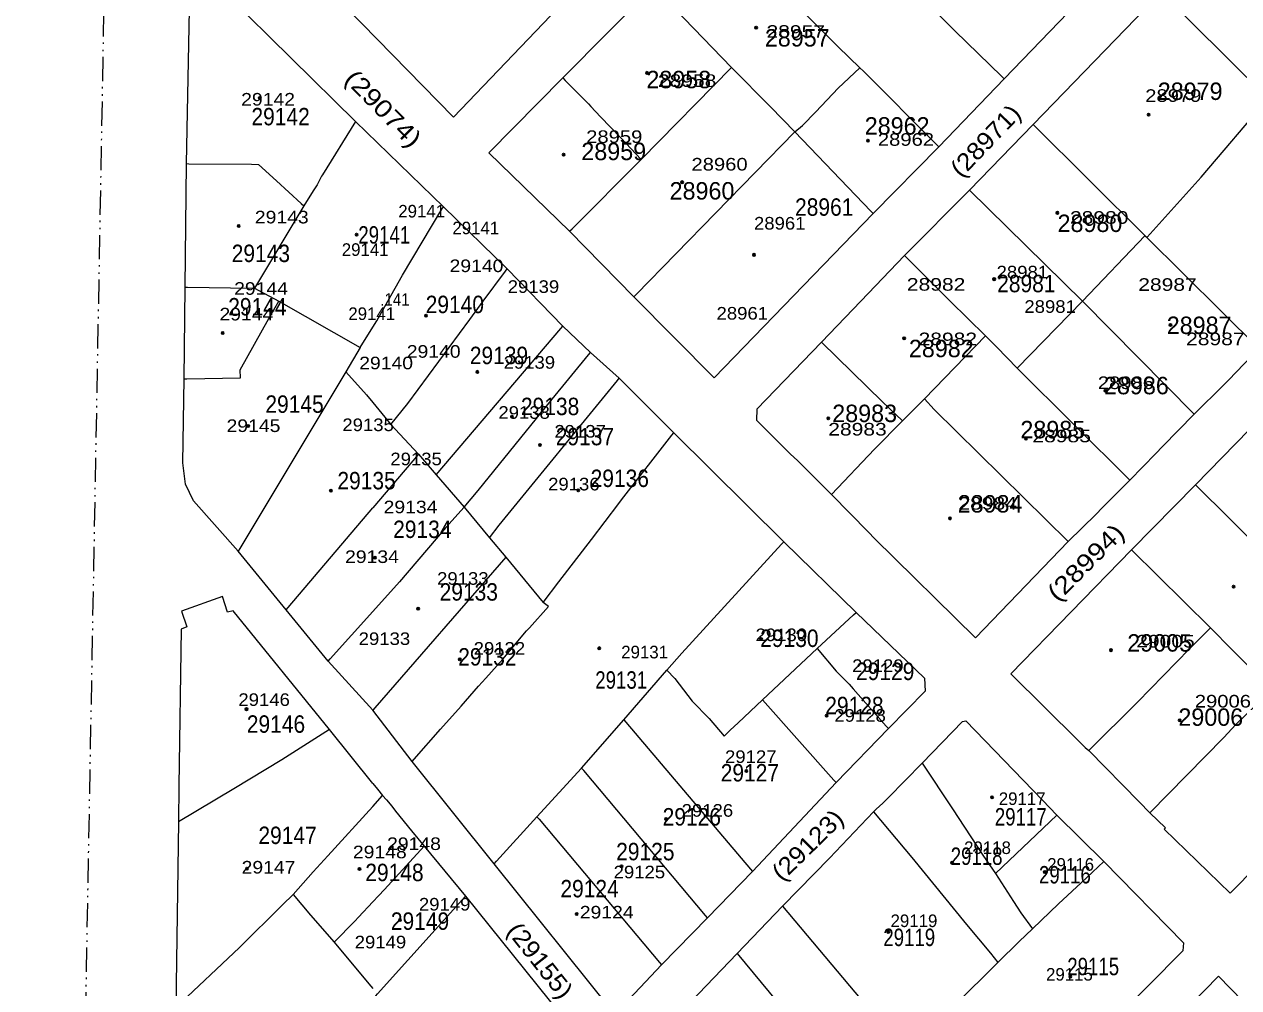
# Model space of a CAD drawing. Extents: x 650553 to 652508, y 239277 to 241647.
# Drawn here: x 650553 to 650803.9, y 240108.2 to 240307.2 of the extents above; entities that cross this region are included whole.
import ezdxf

# ---------------------------------------------------------------- set-up
doc = ezdxf.new("R2010")
doc.units = 0
doc.header["$PDMODE"] = 32
doc.header["$PDSIZE"] = 0.5
doc.linetypes.add('DASH_DOUBLE_DOT', pattern=[9.2, 5, -1.2, 0.3, -1.2, 0.3, -1.2])
for name, color, linetype in [('19', 7, 'Continuous'), ('20', 7, 'Continuous'), ('6', 7, 'Continuous')]:
    doc.layers.add(name, color=color, linetype=linetype)
for name, color, linetype, lineweight in [('3', 7, 'Continuous', 13), ('5', 7, 'Continuous', 13), ('52', 7, 'DASH_DOUBLE_DOT', 13)]:
    doc.layers.add(name, color=color, linetype=linetype, lineweight=lineweight)

msp = doc.modelspace()

# ---------------------------------------------------------------- linework, layer by layer
at = {"layer": '3'}
for p, q in [((650761.43, 240286.46), (650787.85, 240313.79)), ((650585.4, 240182.22), (650584.96, 240149.87)), ((650747.53, 240163.28), (650763.332, 240146.889)), ((650772.9, 240157.17), (650783.334, 240146.554)), ((650584.96, 240149.87), (650584.86, 240142.48)), ((650625, 240150.39), (650625.971, 240149.185)), ((650625.971, 240149.185), (650627.03, 240147.87)), ((650763.332, 240146.889), (650766.31, 240143.8)), ((650783.334, 240146.554), (650785.53, 240144.32))]:
    msp.add_line(p, q, dxfattribs=at)
for points in [[(650783.69, 240471.83), (650801.22, 240451.56), (650782.65, 240432.42), (650769.138, 240418.737), (650755.97, 240405.5), (650742.6, 240391.77), (650729.33, 240378.23), (650715.86, 240364.33), (650702.52, 240350.9), (650689.09, 240337.28), (650675.83, 240323.79), (650664.78, 240312.19), (650641.7, 240288.01), (650622.73, 240307.37), (650608.29, 240321.94)], [(650779.71, 240413.95), (650806.93, 240441.68), (650809.94, 240441.52), (650829.64, 240418.33), (650839.71, 240406.79), (650850.75, 240393.72), (650839.03, 240381.99), (650828.2, 240370.72), (650808.21, 240350.23), (650794.9, 240336.56), (650781.8, 240323.07), (650768.64, 240309.58), (650755.41, 240295.93), (650741.91, 240281.85), (650728.35, 240268.09)], [(650648.95, 240280.64), (650664.24, 240296.1), (650682.98, 240315.02), (650695.81, 240328), (650709.21, 240341.41), (650722.53, 240355.03), (650735.95, 240368.92), (650749.1, 240382.41), (650762.42, 240396.35), (650779.71, 240413.95)], [(650586.52, 240278.39), (650587.14, 240310.13), (650587.44, 240310.18), (650587.09, 240311.44), (650593.87, 240314.16), (650594.4, 240313.05), (650594.86, 240313.35), (650621.45, 240287.07), (650639.57, 240269.49), (650652.76, 240256.68), (650664.23, 240244.84), (650669.94, 240239.41), (650675.92, 240234.11), (650687.16, 240222.82), (650709.87, 240200.29), (650724.82, 240185.65), (650738.96, 240172.09)], [(650725.8, 240250), (650734.8, 240259.41), (650748.27, 240272.9), (650761.43, 240286.46)], [(650728.35, 240268.09), (650695.5, 240234.15), (650678.93, 240250.88), (650665.65, 240264.42), (650648.95, 240280.64)], [(650597.22, 240198.38), (650587.95, 240208.74), (650586.29, 240212.17), (650585.75, 240216.62), (650586.05, 240233.97), (650586.25, 240252.86), (650586.52, 240278.39)], [(650725.8, 240250), (650717.68, 240241.5), (650704.33, 240227.66), (650704.28, 240225.38), (650711.26, 240218.39), (650712.71, 240217.11), (650719.74, 240210.07), (650727.37, 240202.26), (650728.66, 240201), (650749.48, 240180.42), (650768.67, 240200.35), (650774.4, 240206.01), (650775.68, 240207.3), (650781.35, 240212.99), (650786.73, 240218.51), (650788.1, 240219.97), (650794.65, 240226.67), (650800.78, 240232.68), (650801.8, 240233.71), (650808, 240240.22), (650817.4, 240250)], [(650831.89, 240250), (650827.51, 240245.39), (650826.78, 240244.72), (650824.86, 240242.62), (650811.56, 240229.04), (650794.97, 240212.04), (650781.7, 240198.63), (650756.76, 240173.01), (650770.74, 240159.15), (650772.14, 240157.81), (650772.9, 240157.17)], [(650684.63, 240112.92), (650675.75, 240103.49), (650675.1, 240103.3), (650674.4, 240103.48), (650650.06, 240133.8), (650633.1, 240154.9), (650625, 240165.49), (650615.76, 240175.61), (650607.07, 240186.25), (650597.22, 240198.38)], [(650625, 240150.39), (650616.08, 240161.49), (650596.14, 240186.02), (650594.99, 240185.77), (650593.92, 240188.96), (650585.48, 240185.96), (650586.6, 240182.71), (650585.4, 240182.22)], [(650738.96, 240172.09), (650739.08, 240169.46), (650731.5, 240161.73), (650720.7, 240150.55), (650703.44, 240132.18), (650694.13, 240122.61), (650684.63, 240112.92)], [(650738.46, 240154.55), (650746.78, 240163.17), (650747.53, 240163.28)], [(650730.35, 240146.28), (650731.469, 240147.421), (650738.46, 240154.55)], [(650627.03, 240147.87), (650627.81, 240146.98), (650628.91, 240145.67), (650629.67, 240144.63), (650632.98, 240140.56), (650635.6, 240137.45), (650644.17, 240127.09), (650668.82, 240096.43), (650660.31, 240087.35), (650659.16, 240086.06), (650650.76, 240077.36), (650641.23, 240067.58), (650640.54, 240066.69), (650639.28, 240065.35), (650631.76, 240057.45)], [(650722.23, 240045.33), (650706.03, 240065.22), (650694.03, 240079.52), (650692.93, 240080.91), (650681.09, 240095.37), (650690.7, 240105.26), (650700.25, 240115.22), (650709.61, 240125), (650719.43, 240135), (650720.58, 240136.24), (650728.45, 240144.48), (650729.01, 240145.07), (650730.35, 240146.28)], [(650785.53, 240144.32), (650788.76, 240141.22), (650788.44, 240140.92), (650802.1, 240127.68), (650807.72, 240133.44), (650807.48, 240133.9), (650818.42, 240144.86)], [(650584.86, 240142.48), (650584.29, 240104.07), (650583.64, 240060.91)], [(650766.31, 240143.8), (650775.98, 240134.27), (650792.47, 240117.44), (650792.29, 240115.83), (650763.49, 240086.71), (650744.41, 240067.5), (650736.33, 240059.47), (650735.05, 240058.07), (650734.43, 240057.51), (650722.23, 240045.33)], [(650791.13, 240101.84), (650799.66, 240110.57), (650812.24, 240097.72)]]:
    msp.add_lwpolyline(points, dxfattribs=at)
at = {"layer": '5'}
for p, q in [((650748.27, 240272.9), (650771.6, 240250)), ((650784.48, 240263.5), (650771.6, 240250)), ((650734.8, 240259.41), (650744.29, 240250)), ((650628.12, 240250), (650631.11, 240255.33)), ((650758.13, 240236.16), (650771.6, 240250)), ((650771.6, 240250), (650794.65, 240226.67)), ((650622.4, 240240.42), (650619.4, 240235.41)), ((650634.41, 240218.37), (650625, 240207.31)), ((650649.13, 240201.13), (650651.11, 240203.69)), ((650685.71, 240173.76), (650688.84, 240177.29)), ((650625, 240145.64), (650627.03, 240147.87)), ((650753.65, 240131.76), (650766.31, 240143.8))]:
    msp.add_line(p, q, dxfattribs=at)
for points in [[(650709.21, 240341.41), (650709.71, 240340.917), (650732.07, 240318.85), (650737.83, 240313.19), (650745.26, 240305.8)], [(650695.81, 240328), (650696.307, 240327.5), (650717.06, 240306.61), (650721.14, 240302.53), (650725.63, 240298.21), (650726.33, 240297.51)], [(650784.94, 240263.21), (650796.11, 240275.63), (650809.97, 240291.87), (650823.52, 240304.87), (650836.94, 240317.85)], [(650682.98, 240315.02), (650683.461, 240314.52), (650699.12, 240298.24), (650707.18, 240290.13), (650712.21, 240284.96)], [(650787.85, 240313.79), (650801.15, 240300.62), (650809.97, 240291.87), (650834.26, 240267.54)], [(650745.26, 240305.8), (650754.91, 240296.416), (650755.41, 240295.93)], [(650665.65, 240264.42), (650666.148, 240264.92), (650680.45, 240279.27), (650699.12, 240298.24)], [(650712.21, 240284.96), (650713.76, 240286.28), (650716.53, 240289.09), (650721.14, 240293.99), (650725.63, 240298.21)], [(650726.33, 240297.51), (650741.413, 240282.35), (650741.91, 240281.85)], [(650664.24, 240296.1), (650664.733, 240295.6), (650669.52, 240290.74), (650670.06, 240290.18), (650672.04, 240288.05), (650676.2, 240283.72), (650680.45, 240279.27)], [(650621.45, 240287.07), (650614.62, 240276.09), (650614.38, 240275.8), (650614.11, 240275.29), (650613.51, 240274.05), (650612.65, 240272.8), (650610.73, 240269.71), (650600.55, 240252.65), (650605.56, 240250)], [(650678.93, 240250.88), (650679.418, 240251.38), (650712.21, 240284.96)], [(650712.21, 240284.96), (650727.872, 240268.59), (650728.35, 240268.09)], [(650761.43, 240286.46), (650784.682, 240263.372), (650808, 240240.22)], [(650586.52, 240278.39), (650587.02, 240278.386), (650599.97, 240278.29), (650601.42, 240278.23), (650605.11, 240274.84), (650610.23, 240270.166), (650610.73, 240269.71)], [(650631.11, 240255.33), (650639.271, 240268.99), (650639.57, 240269.49)], [(650784.48, 240263.5), (650784.682, 240263.372), (650784.94, 240263.21)], [(650647.82, 240250), (650652.39, 240256.18), (650652.76, 240256.68)], [(650586.25, 240252.86), (650586.75, 240252.853), (650600.05, 240252.657), (650600.55, 240252.65)], [(650586.05, 240233.97), (650586.55, 240233.979), (650597.65, 240234.18), (650597.59, 240235.79), (650603.53, 240246.38), (650605.56, 240250)], [(650605.56, 240250), (650622.4, 240240.42), (650625, 240244.6)], [(650625, 240244.6), (650625.84, 240245.95), (650628.12, 240250)], [(650628.75, 240224.5), (650632.23, 240228.86), (650645.03, 240246.23), (650647.82, 240250)], [(650744.29, 240250), (650751.53, 240242.83), (650753.87, 240240.5), (650758.13, 240236.16), (650781.35, 240212.99)], [(650638.08, 240214.09), (650663.805, 240244.34), (650664.23, 240244.84)], [(650719.74, 240210.07), (650728.65, 240219.44), (650734.43, 240225.26), (650738.95, 240229.79), (650751.53, 240242.83)], [(650662.08, 240229.72), (650669.534, 240238.91), (650669.94, 240239.41)], [(650717.68, 240241.5), (650730.31, 240229.17), (650734.43, 240225.26)], [(650619.4, 240235.41), (650597.519, 240198.88), (650597.22, 240198.38)], [(650619.4, 240235.41), (650623.72, 240230.66), (650625, 240229.09)], [(650651.11, 240203.69), (650675.512, 240233.61), (650675.92, 240234.11)], [(650643.85, 240207.42), (650646.79, 240210.87), (650662.08, 240229.72)], [(650738.95, 240229.79), (650740.98, 240227.59), (650768.67, 240200.35)], [(650625, 240229.09), (650628.75, 240224.5), (650630.61, 240222.52), (650634.41, 240218.37), (650638.08, 240214.09), (650643.85, 240207.42), (650649.13, 240201.13), (650652.5, 240197.09), (650660.18, 240187.72)], [(650676.36, 240208.98), (650686.77, 240222.32), (650687.16, 240222.82)], [(650794.97, 240212.04), (650816.57, 240190.66), (650824.01, 240183.28), (650840.42, 240167.09)], [(650607.07, 240186.25), (650607.496, 240186.75), (650625, 240207.31)], [(650643.85, 240207.42), (650640.08, 240203.25), (650630.5, 240192.02), (650625, 240185.9)], [(650633.1, 240154.9), (650633.542, 240155.4), (650639.01, 240161.58), (650643.26, 240166.37), (650646.85, 240170.44), (650648.37, 240172.11), (650651.87, 240176.06), (650656.74, 240181.88), (650657.38, 240182.53), (650661.29, 240186.89), (650660.18, 240187.72), (650663.42, 240192), (650670.18, 240200.77), (650675.85, 240208.18), (650676.36, 240208.98)], [(650688.84, 240177.29), (650709.413, 240199.79), (650709.87, 240200.29)], [(650652.5, 240197.09), (650625.435, 240165.99), (650625, 240165.49)], [(650781.7, 240198.63), (650798.02, 240182.54), (650802.52, 240177.97), (650810.6, 240169.99), (650808.01, 240167.19), (650807.31, 240166.49), (650824.01, 240150.65)], [(650615.76, 240175.61), (650616.209, 240176.11), (650625, 240185.9)], [(650716.79, 240178.22), (650724.32, 240185.187), (650724.82, 240185.65)], [(650772.9, 240157.17), (650782.96, 240167.19), (650793.69, 240178.18), (650798.02, 240182.54)], [(650685.71, 240173.76), (650687.38, 240172.02), (650691, 240167.39), (650694.45, 240163.8), (650697.55, 240160.11), (650698.8, 240161.37), (650700.44, 240162.91), (650705.47, 240167.63), (650716.79, 240178.22)], [(650716.79, 240178.22), (650720.7, 240173.58), (650723.42, 240170.85), (650724.23, 240169.89)], [(650650.06, 240133.8), (650650.517, 240134.3), (650658.91, 240143.49), (650668.14, 240153.56), (650676.86, 240163.5), (650685.71, 240173.76)], [(650724.23, 240169.89), (650731.055, 240162.23), (650731.5, 240161.73)], [(650705.47, 240167.63), (650720.254, 240151.05), (650720.7, 240150.55)], [(650785.53, 240144.32), (650800.78, 240159.87), (650803.27, 240162.56), (650807.31, 240166.49)], [(650616.08, 240161.49), (650606.19, 240155.28), (650596.26, 240149.23), (650584.86, 240142.48)], [(650676.86, 240163.5), (650677.284, 240163), (650703.016, 240132.68), (650703.44, 240132.18)], [(650738.46, 240154.55), (650744.74, 240145.12), (650751.03, 240135.56), (650753.65, 240131.76), (650757.32, 240126.02), (650758.86, 240123.64), (650761.29, 240120.34)], [(650694.13, 240122.61), (650693.71, 240123.11), (650668.56, 240153.06), (650668.14, 240153.56)], [(650584.29, 240104.07), (650597.45, 240116.5), (650606.31, 240125.29), (650608.58, 240127.45), (650612.66, 240132.09), (650615.73, 240135.44), (650625, 240145.64)], [(650728.45, 240144.48), (650736.35, 240135.05), (650747.62, 240121.24), (650752.6, 240115.32), (650754.11, 240113.42)], [(650658.91, 240143.49), (650659.331, 240142.99), (650684.209, 240113.42), (650684.63, 240112.92)], [(650625, 240125.89), (650626.18, 240127.14), (650627.39, 240128.48), (650635.6, 240137.45)], [(650715.45, 240074.54), (650713.99, 240076.53), (650712.37, 240078.72), (650710.08, 240081.83), (650720.2, 240091.4), (650722, 240089.82), (650725.8, 240086.02), (650726.2, 240086.53), (650734.98, 240094.96), (650745.18, 240104.53), (650754.11, 240113.42), (650758.53, 240117.73), (650761.29, 240120.34), (650766.61, 240125.54), (650771.3, 240129.83), (650775.98, 240134.27)], [(650608.58, 240127.45), (650612.15, 240123.17), (650617, 240117.56), (650624.19, 240109.01), (650625, 240108.05)], [(650625, 240105.88), (650625.61, 240106.54), (650625.96, 240106.92), (650644.17, 240127.09)], [(650625, 240125.89), (650622.01, 240122.75), (650621.32, 240121.94), (650617, 240117.56)], [(650709.61, 240125), (650732.2, 240098.15), (650734.98, 240094.96)], [(650700.25, 240115.22), (650713.51, 240099.27), (650720.2, 240091.4)]]:
    msp.add_lwpolyline(points, dxfattribs=at)
at = {"layer": '52'}
msp.add_lwpolyline([(650605.404, 240765.589), (650575.102, 240622.376), (650564.111, 240019.547), (650563.292, 239912.239), (650561.967, 239831.306), (650558.948, 239635.138), (650557.76, 239590.469), (650555.824, 239499.761), (650555.114, 239481.758), (650553.994, 239393.396), (650554.019, 239393.395), (650553.222, 239318.763), (650553.006, 239301.006), (650586.911, 239277.281)], dxfattribs=at)
at = {"layer": '6'}
for p in [(650704.192, 240306.48), (650681.659, 240297.145), (650601.656, 240291.935), (650785.248, 240288.5), (650727.279, 240283.15), (650664.423, 240280.26), (650688.905, 240274.56), (650766.409, 240268.23), (650597.307, 240265.52), (650621.654, 240263.745), (650703.745, 240259.555), (650753.353, 240254.53), (650636.012, 240246.995), (650789.778, 240245.085), (650594.008, 240243.415), (650734.765, 240242.335), (650646.614, 240235.385), (650776.344, 240231.495), (650599.28, 240224.19), (650653.743, 240226.13), (650719.083, 240225.785), (650759.905, 240221.59), (650659.523, 240220.27), (650616.336, 240210.83), (650667.436, 240210.915), (650744.214, 240205.105), (650625.477, 240196.99), (650802.818, 240191.015), (650634.372, 240186.455), (650705.215, 240180.2), (650671.763, 240178.31), (650777.468, 240177.9), (650642.977, 240175.995), (650728.949, 240173.69), (650598.909, 240165.72), (650718.749, 240164.385), (650791.675, 240163.43), (650702.169, 240152.97), (650752.933, 240147.52), (650685.586, 240143.055), (650744.668, 240133.985), (650599.004, 240132.78), (650622.249, 240132.715), (650676.369, 240133.24), (650763.819, 240132.07), (650630.635, 240122.185), (650667.115, 240123.395), (650731.475, 240119.72), (650769.088, 240110.49)]:
    msp.add_point(p, dxfattribs=at)

# ---------------------------------------------------------------- texts
at = {"layer": '19'}
for s, p in [('28957', (650705.982, 240302.584)), ('28958', (650681.509, 240293.965)), ('28979', (650787.143, 240291.546)), ('28962', (650726.617, 240284.387)), ('28959', (650668.072, 240279.12)), ('28960', (650686.308, 240270.979)), ('28980', (650766.448, 240264.276)), ('28987', (650789.002, 240243.205)), ('28982', (650735.737, 240238.417)), ('28986', (650776.046, 240230.755)), ('28983', (650719.901, 240225.009)), ('28985', (650758.77, 240221.657)), ('28984', (650745.813, 240206.333)), ('29005', (650780.845, 240177.602)), ('29006', (650791.403, 240162.278))]:
    msp.add_text(s, height=3.6, dxfattribs=at).set_placement(p)
for s, rotation, width, p in [('(29074)', 314.426, 1.2, (650618.912, 240295.626)), ('(28971)', 46.13, 1.1, (650746.541, 240275.299)), ('(28994)', 44.912, 1.2, (650766.483, 240187.727)), ('(29123)', 44.491, 1.1, (650709.564, 240129.968)), ('(29155)', 308.341, 1.1, (650652.487, 240119.846))]:
    msp.add_text(s, height=3.6, rotation=rotation, dxfattribs=dict(at, width=width)).set_placement(p)
for s, width, p in [('29142', 0.9, (650599.931, 240286.303)), ('28961', 0.9, (650712.221, 240267.627)), ('29141', 0.8, (650622.005, 240261.881)), ('29143', 0.9, (650595.852, 240258.065)), ('28981', 0.9, (650753.972, 240251.825)), ('29144', 0.9, (650595.132, 240247.037)), ('29140', 0.9, (650635.921, 240247.516)), ('29139', 0.9, (650645.039, 240236.981)), ('29145', 0.9, (650602.811, 240226.925)), ('29138', 0.9, (650655.597, 240226.446)), ('29137', 0.9, (650662.795, 240220.22)), ('29135', 0.9, (650617.687, 240211.122)), ('29136', 0.9, (650669.993, 240211.601)), ('29134', 0.9, (650629.203, 240201.066)), ('29133', 0.9, (650638.801, 240188.137)), ('29130', 0.9, (650705.023, 240178.56)), ('29132', 0.9, (650642.64, 240174.729)), ('29129', 0.9, (650724.818, 240171.728)), ('29131', 0.8, (650670.953, 240169.94)), ('29128', 0.9, (650718.459, 240164.673)), ('29146', 0.9, (650598.973, 240160.842)), ('29127', 0.9, (650696.865, 240150.786)), ('29126', 0.9, (650684.868, 240141.687)), ('29117', 0.8, (650753.489, 240141.687)), ('29147', 0.9, (650601.372, 240137.856)), ('29125', 0.9, (650675.27, 240134.504)), ('29118', 0.8, (650744.371, 240133.547)), ('29148', 0.9, (650623.445, 240130.195)), ('29116', 0.8, (650762.606, 240129.716)), ('29124', 0.9, (650663.752, 240126.842)), ('29149', 0.9, (650628.725, 240120.138)), ('29119', 0.8, (650730.455, 240116.786)), ('29115', 0.8, (650768.453, 240110.763))]:
    msp.add_text(s, height=3.6, dxfattribs=dict(at, width=width)).set_placement(p)
at = {"layer": '20'}
for s, width, p in [('28957', 1.25, (650706.319, 240304.39)), ('28958', 1.25, (650683.884, 240294.234)), ('29142', 1.15, (650597.808, 240290.387)), ('28979', 1.2, (650784.554, 240291.149)), ('28959', 1.2, (650669.077, 240282.666)), ('28962', 1.2, (650729.328, 240282.082)), ('28960', 1.2, (650690.826, 240276.97)), ('29143', 1.15, (650600.632, 240266.049)), ('28961', 1.1, (650703.74, 240264.778)), ('28980', 1.25, (650769.005, 240265.977)), ('29140', 1.15, (650640.856, 240255.992)), ('28981', 1.1, (650753.86, 240254.69)), ('29139', 1.1, (650652.867, 240251.697)), ('28982', 1.25, (650735.314, 240252.155)), ('28987', 1.25, (650783.112, 240252.118)), ('29144', 1.15, (650596.354, 240251.308)), ('.141', 0.9, (650626.523, 240249.027)), ('28981', 1.1, (650759.593, 240247.573)), ('29144', 1.15, (650593.326, 240246.007)), ('28961', 1.1, (650696.005, 240246.184)), ('28982', 1.25, (650737.735, 240240.89)), ('28987', 1.25, (650792.995, 240240.89)), ('29140', 1.15, (650632.017, 240238.304)), ('29140', 1.15, (650622.187, 240235.919)), ('29139', 1.1, (650652.019, 240236.04)), ('28986', 1.2, (650774.765, 240231.834)), ('29138', 1.1, (650650.941, 240225.692)), ('29145', 1.15, (650594.794, 240222.963)), ('29135', 1.1, (650618.709, 240223.148)), ('29137', 1.1, (650662.517, 240221.811)), ('28983', 1.25, (650719.075, 240222.24)), ('28985', 1.25, (650761.254, 240220.839)), ('29135', 1.1, (650628.621, 240216.097)), ('29136', 1.1, (650661.214, 240210.904)), ('28984', 1.25, (650745.964, 240206.933)), ('29134', 1.15, (650627.233, 240206.18)), ('29134', 1.15, (650619.268, 240195.909)), ('29133', 1.1, (650638.277, 240191.411)), ('29133', 1.1, (650622.08, 240178.973)), ('29130', 1.1, (650704.064, 240179.769)), ('29132', 1.1, (650645.837, 240176.966)), ('29005', 1.25, (650782.69, 240178.458)), ('29129', 1.1, (650724.012, 240173.409)), ('29146', 1.1, (650597.231, 240166.387)), ('29006', 1.2, (650794.8, 240166.061)), ('29128', 1.1, (650720.344, 240163.122)), ('29127', 1.1, (650697.759, 240154.606)), ('29126', 1.1, (650688.797, 240143.503)), ('29148', 1.15, (650627.949, 240136.628)), ('29148', 1.15, (650620.887, 240134.921)), ('29147', 1.15, (650597.899, 240131.767)), ('29125', 1.1, (650674.747, 240130.782)), ('29149', 1.1, (650634.522, 240124.123)), ('29124', 1.15, (650667.755, 240122.482)), ('29149', 1.1, (650621.26, 240116.311))]:
    msp.add_text(s, height=2.6, dxfattribs=dict(at, width=width)).set_placement(p)
for s, p in [('29141', (650630.259, 240267.272)), ('29141', (650641.432, 240263.805)), ('29141', (650618.588, 240259.343)), ('29141', (650619.944, 240246.1)), ('29131', (650676.316, 240176.211)), ('29117', (650754.302, 240145.933)), ('29118', (650747.145, 240135.8)), ('29116', (650764.307, 240132.351)), ('29119', (650731.95, 240120.708)), ('29115', (650764.063, 240109.643))]:
    msp.add_text(s, height=2.6, dxfattribs=at).set_placement(p)

doc.saveas('drawing.dxf')
